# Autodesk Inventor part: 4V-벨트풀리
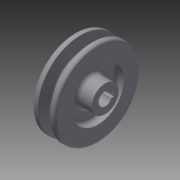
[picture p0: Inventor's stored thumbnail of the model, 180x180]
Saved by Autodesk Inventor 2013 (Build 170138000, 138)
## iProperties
Created: 2015-02
Part Number: 4V-벨트풀리
Material: 일반
Document SubType Name: Modeling
Designer: Administrator
Density: 1 g/cm^3
Author: Administrator
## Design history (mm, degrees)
sketch "스케치1"
  geometry: L1 (-12.5, 0)-(12.5, 0); L2 (-12.5, 0)-(-12.5, 11); L3 (0.5, 11)-(12.5, 11); L4 (-14.536, 32.5)-(16.476, 32.5); L5 (-12.5, 11)-(-6.5, 11); L6 (-6.5, 11)-(-6.5, 21.5); L7 (-6.5, 21.5)-(-12.5, 21.5); L8 (-12.5, 21.5)-(-12.5, 35.2); L9 (-12.5, 35.2)-(-7.825, 35.2); L10 (-0.926, 26.2)-(-5.074, 26.2); L11 (1.825, 35.2)-(6.5, 35.2); L12 (6.5, 35.2)-(6.5, 21.5); L13 (6.5, 21.5)-(0.5, 21.5); L14 (0.5, 21.5)-(0.5, 11); L15 (-3.544, 32.5)-(1.256, 32.5); L16 (-7.825, 35.2)-(-5.074, 26.2); L17 (1.825, 35.2)-(-0.926, 26.2); L18 (12.5, 11)-(12.5, 0); L19 (-12.5, 0)-(12.5, 0); L20 (-12.5, 11)-(-6.5, 11); 5 further points
  constraints: 40 end point, 9 parallel, 4 midpoint, 4 perpendicular, 2 collinear, 2 equal length, 2 point on line, 1 coincident, 1 horizontal, 1 horizontal alignment, 1 vertical alignment
  dimensions: "d0" = 25 distance of L1.start L1.end; "d3" = 22 diameter of L3 L1; "d4" = 65 diameter of L4 L1; "d5" = 6 distance between parallel lines of L12 L14; "d6" = 6 distance between parallel lines of L8 L6; "d7" = 19 distance from line of L8.end L12; "d9" = 2.7 distance between parallel lines of L4 L9; "d12" = 6.3 distance between parallel lines of L4 L10; "d13" = 34 deg angle of L16 L17; "d14" = 43 diameter of L7 L1; "d16" = 4.14779 distance of L10.start L10.end
revolve "회전1" sketch "스케치1" stored, may be unused: angle "d17" = 90 deg
sketch "스케치2"
  geometry: C1 r 11 at (0, 0) reference; 1 further point
  constraints: 1 coincident
hole "구멍1" sketch "스케치2" at (0, 0) diameter "d18" = 11; stored, may be unused: countersink angle "d22" = 90 deg, drill point angle "d24" = 0 deg; dims "d19" = 6, "d20" = 4, "d21" = 2, "d23" = 25
sketch "스케치3"
  geometry: L1 (-2, 7.3)-(2, 7.3); L2 (2, 7.3)-(2, 0); L3 (2, 0)-(-2, 0); L4 (-2, 0)-(-2, 7.3); C1 r 5.5 at (0, 0) reference; 1 further point
  constraints: 8 end point, 2 parallel, 1 coincident, 1 horizontal, 1 midpoint, 1 perpendicular
  dimensions: "d25" = 4 distance of L1.start L1.end; "d27" = 7.3 distance from line of C1.centre L1
extrude "돌출1" cut sketch "스케치3" distance "d28" = 25; taper "d29" = 0 deg
fillet "모깎기1" dims "d30" = 1, "d31" = 0.5, "d32" = 2
fillet "모깎기2" dims "d33" = 1, "d34" = 0.5, "d35" = 2
fillet "모깎기3" dims "d36" = 3
fillet "모깎기4" dims "d37" = 3
node "솔리드1"
